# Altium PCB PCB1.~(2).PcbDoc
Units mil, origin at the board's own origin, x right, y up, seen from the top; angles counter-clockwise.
Board outline 1968 x 1968 mil, 4 copper layers (Top Layer, Internal Plane 1, Internal Plane 2, Bottom Layer), stack 18.2 mil thick; 12 components, 11 nets, 37 pads, 0 vias.
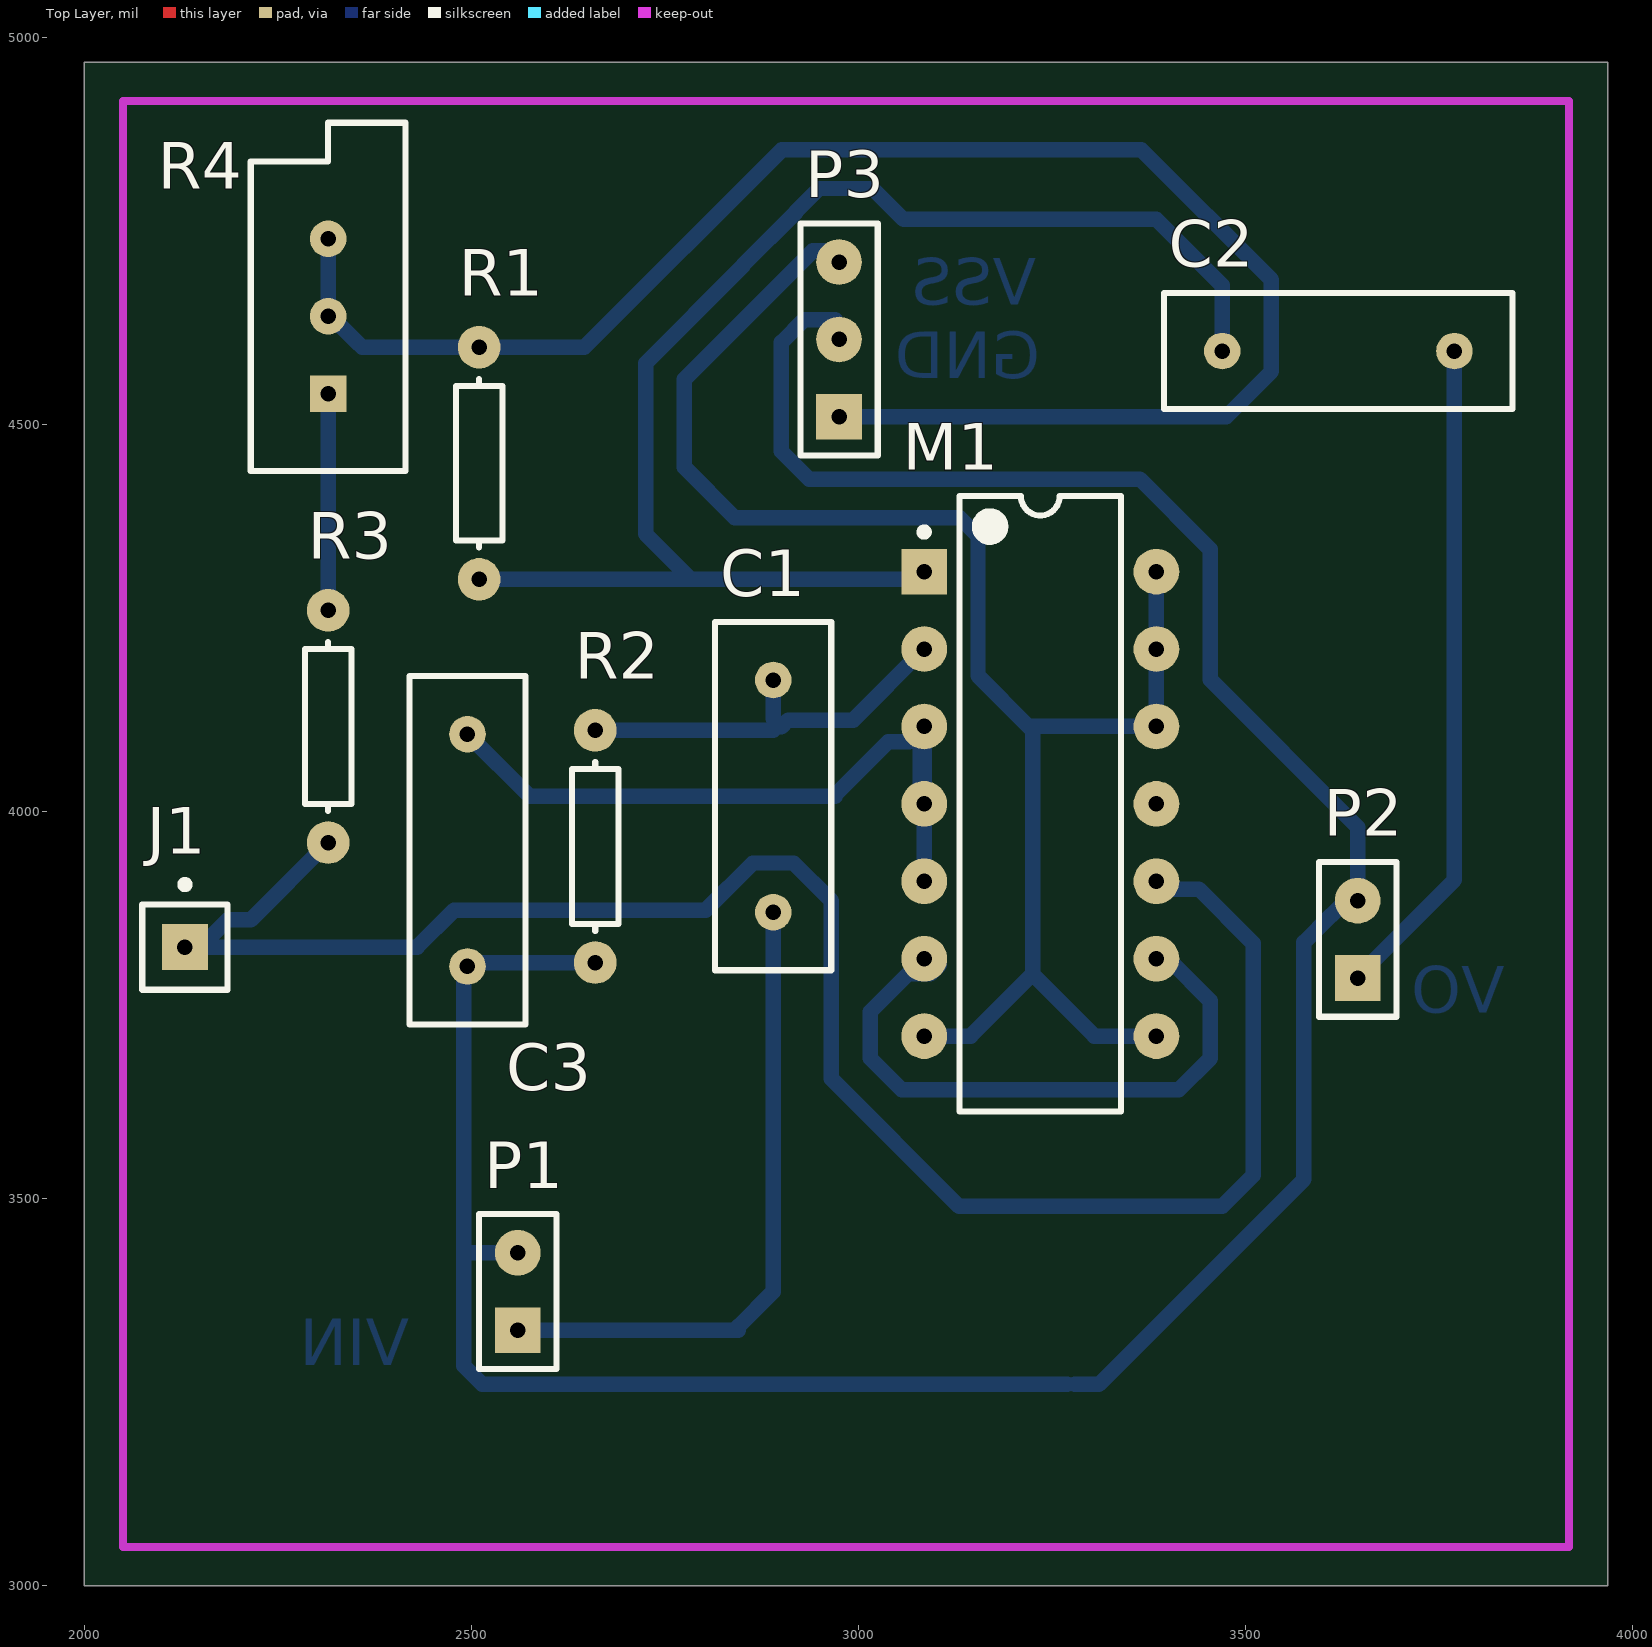
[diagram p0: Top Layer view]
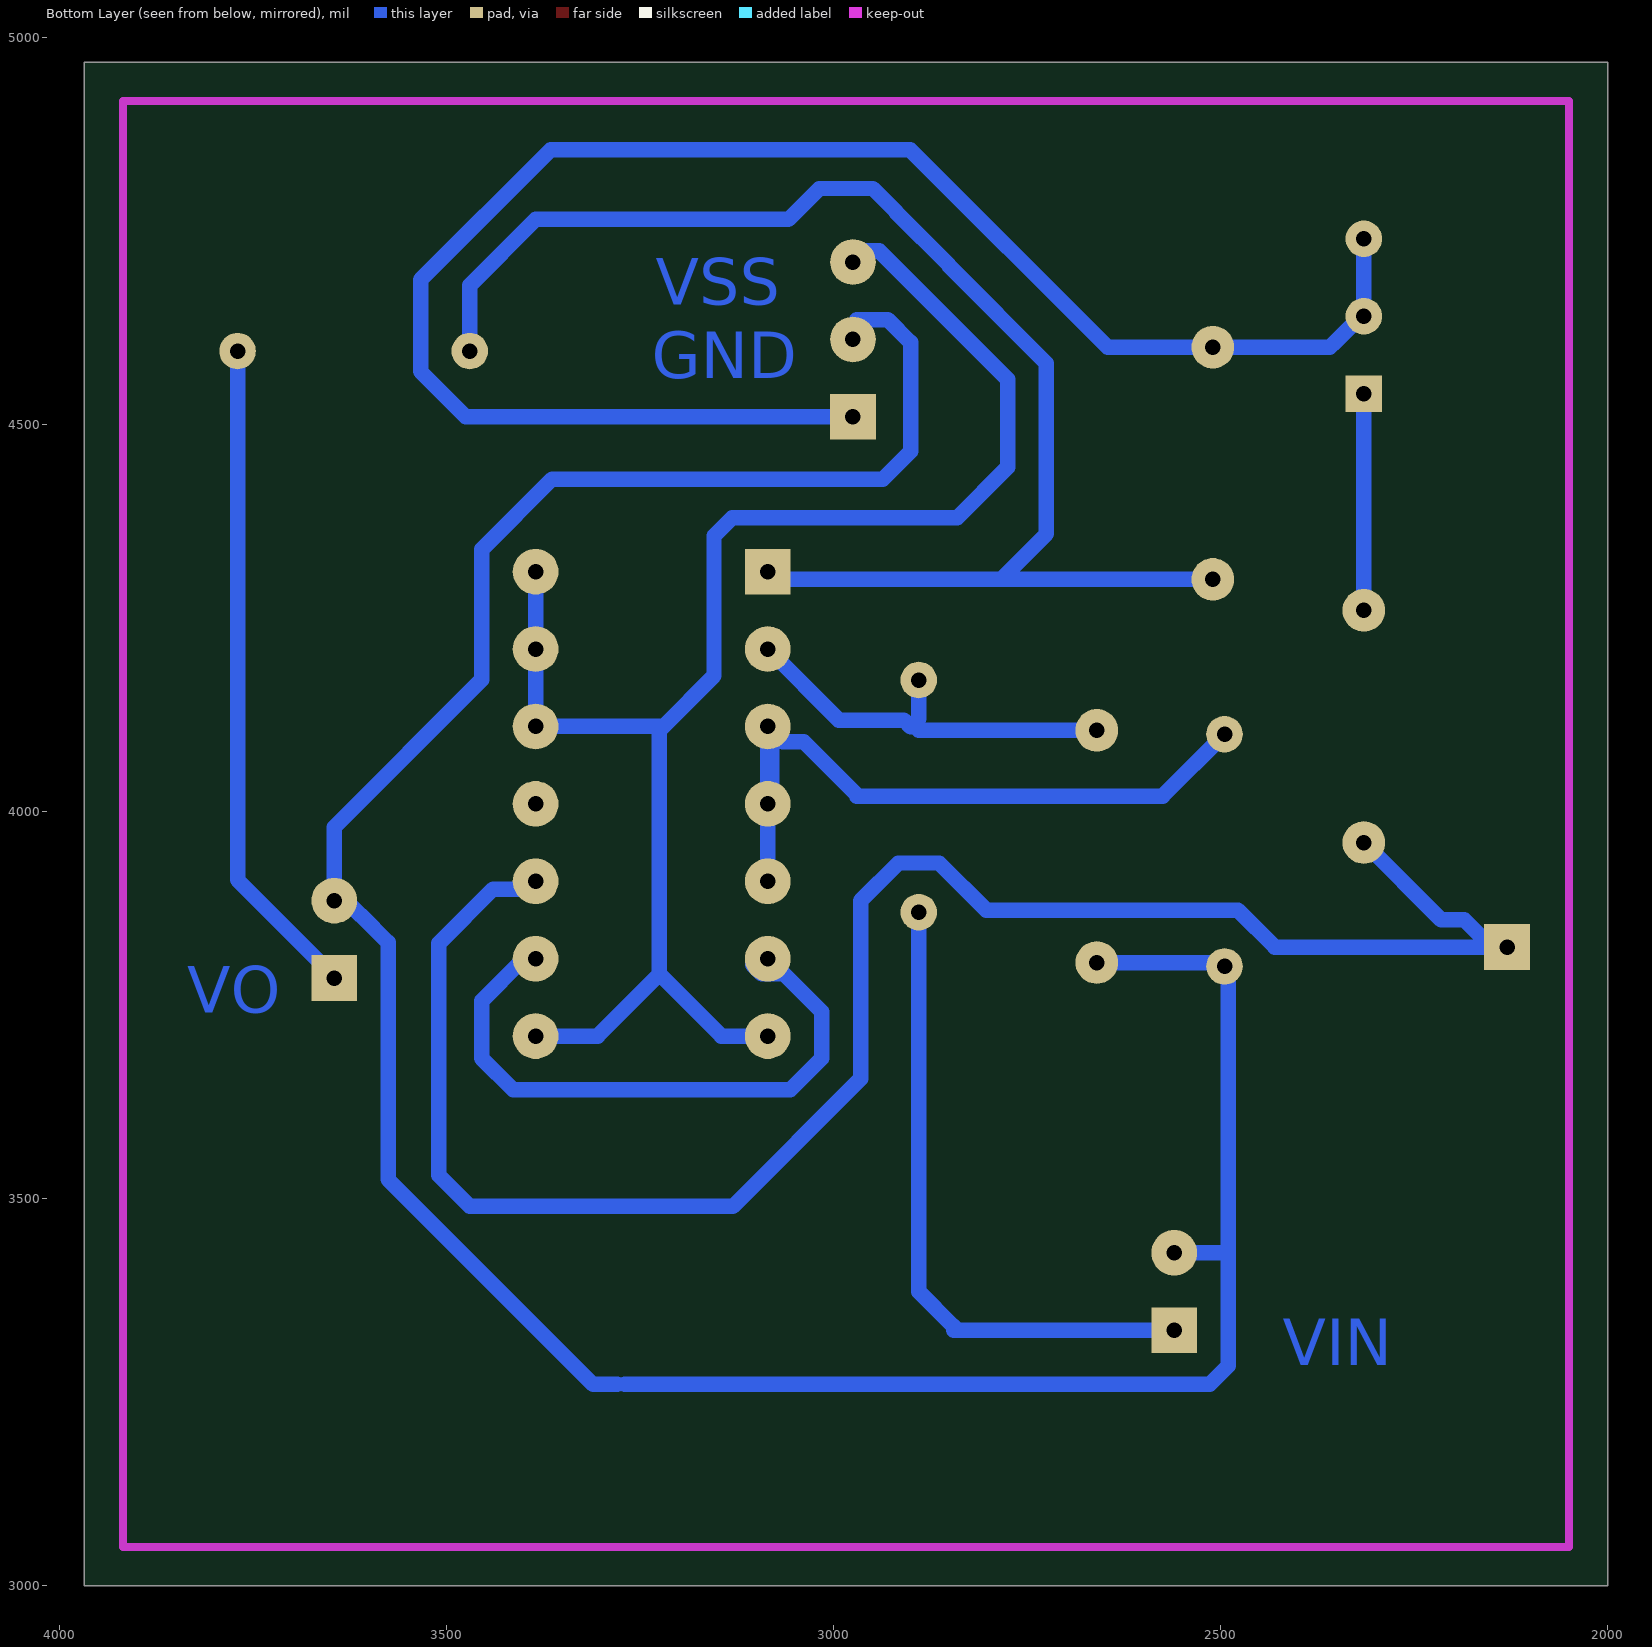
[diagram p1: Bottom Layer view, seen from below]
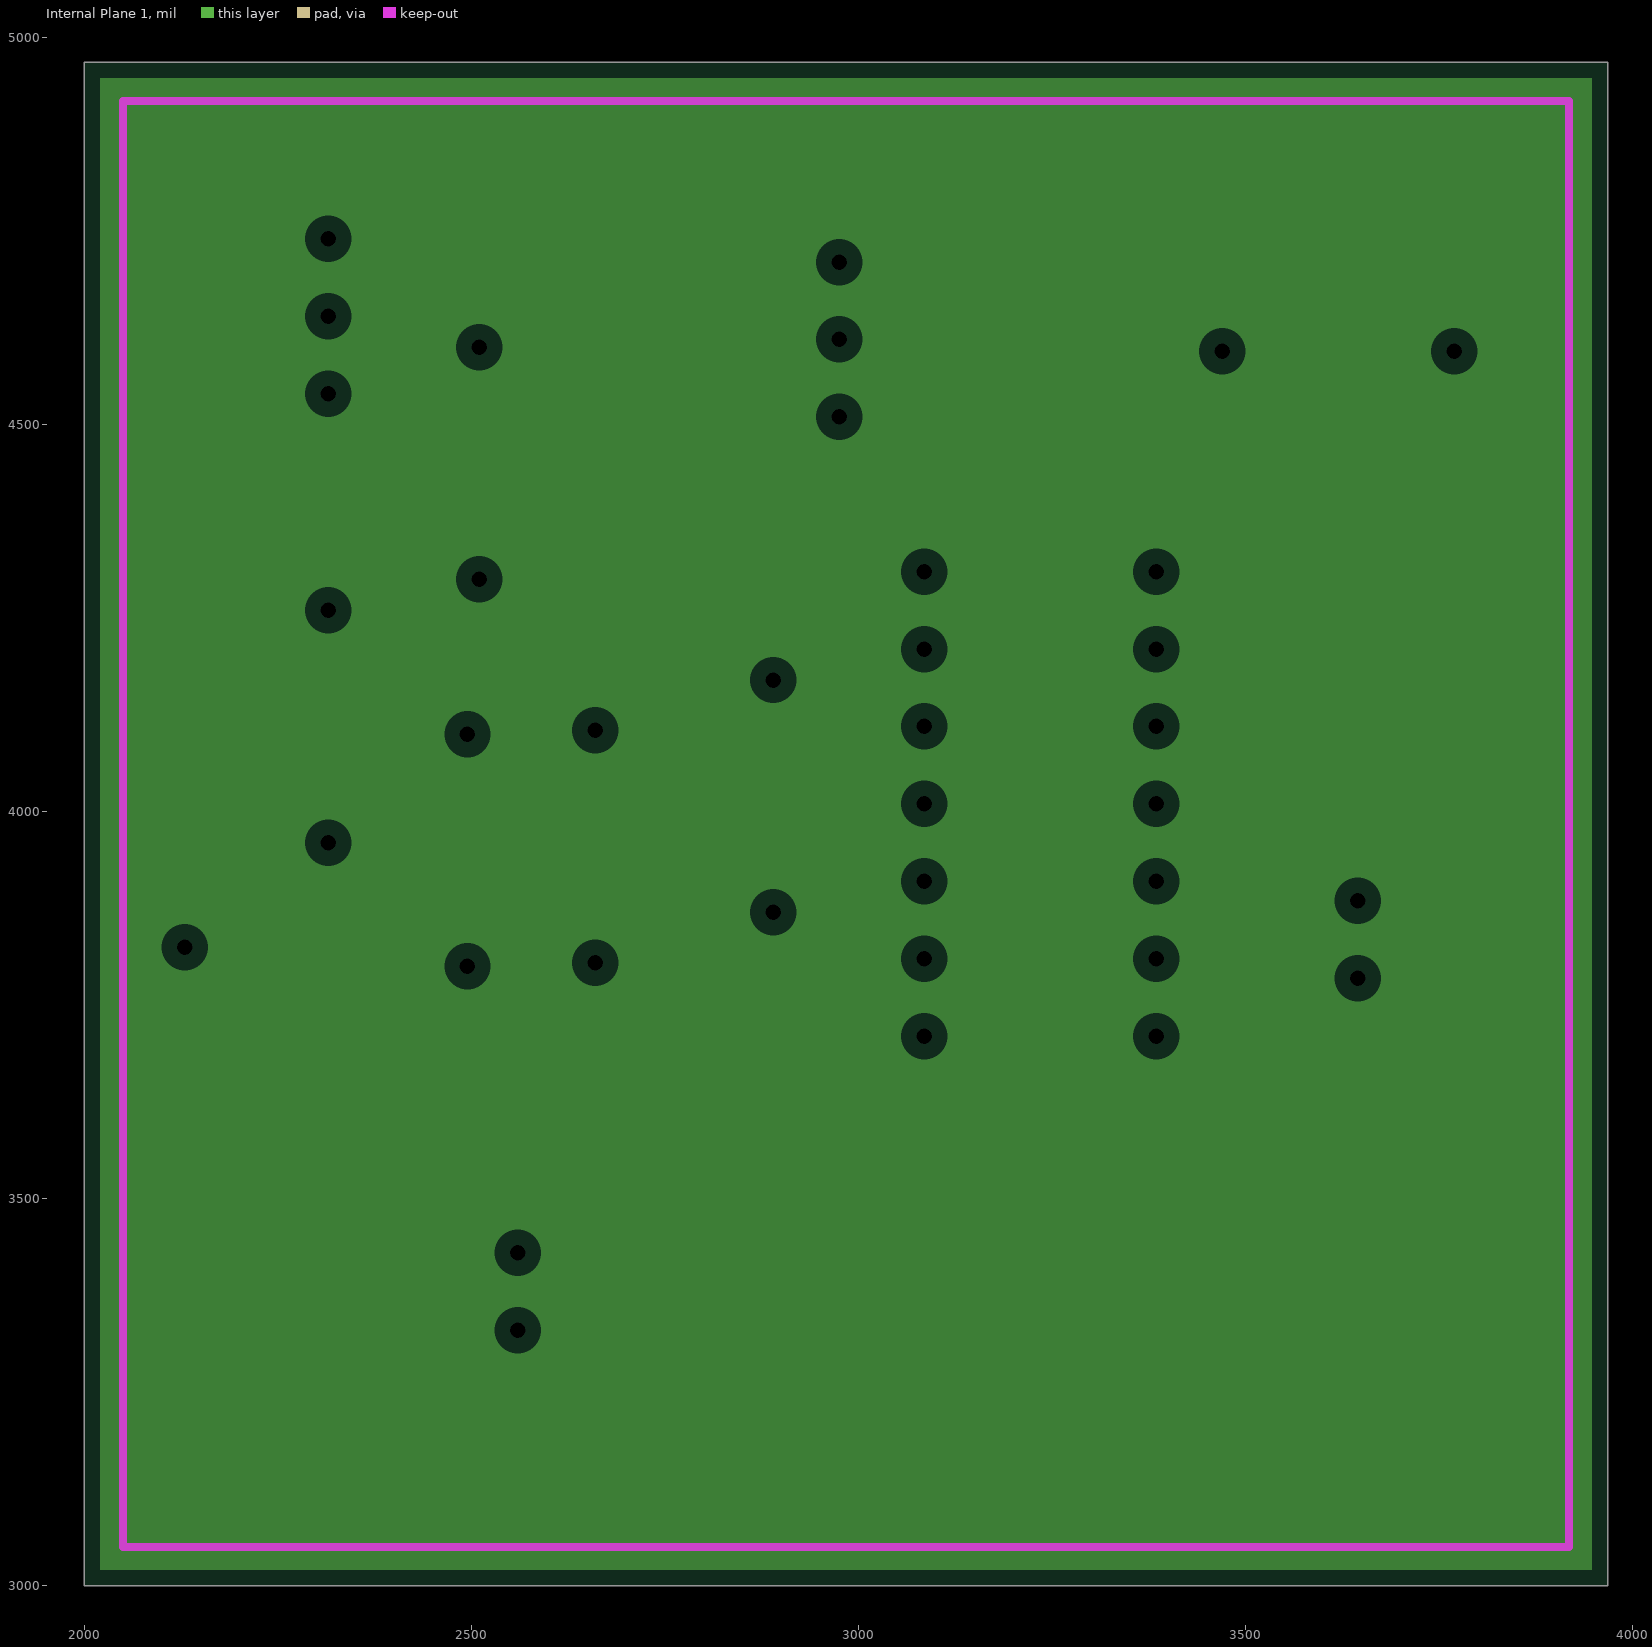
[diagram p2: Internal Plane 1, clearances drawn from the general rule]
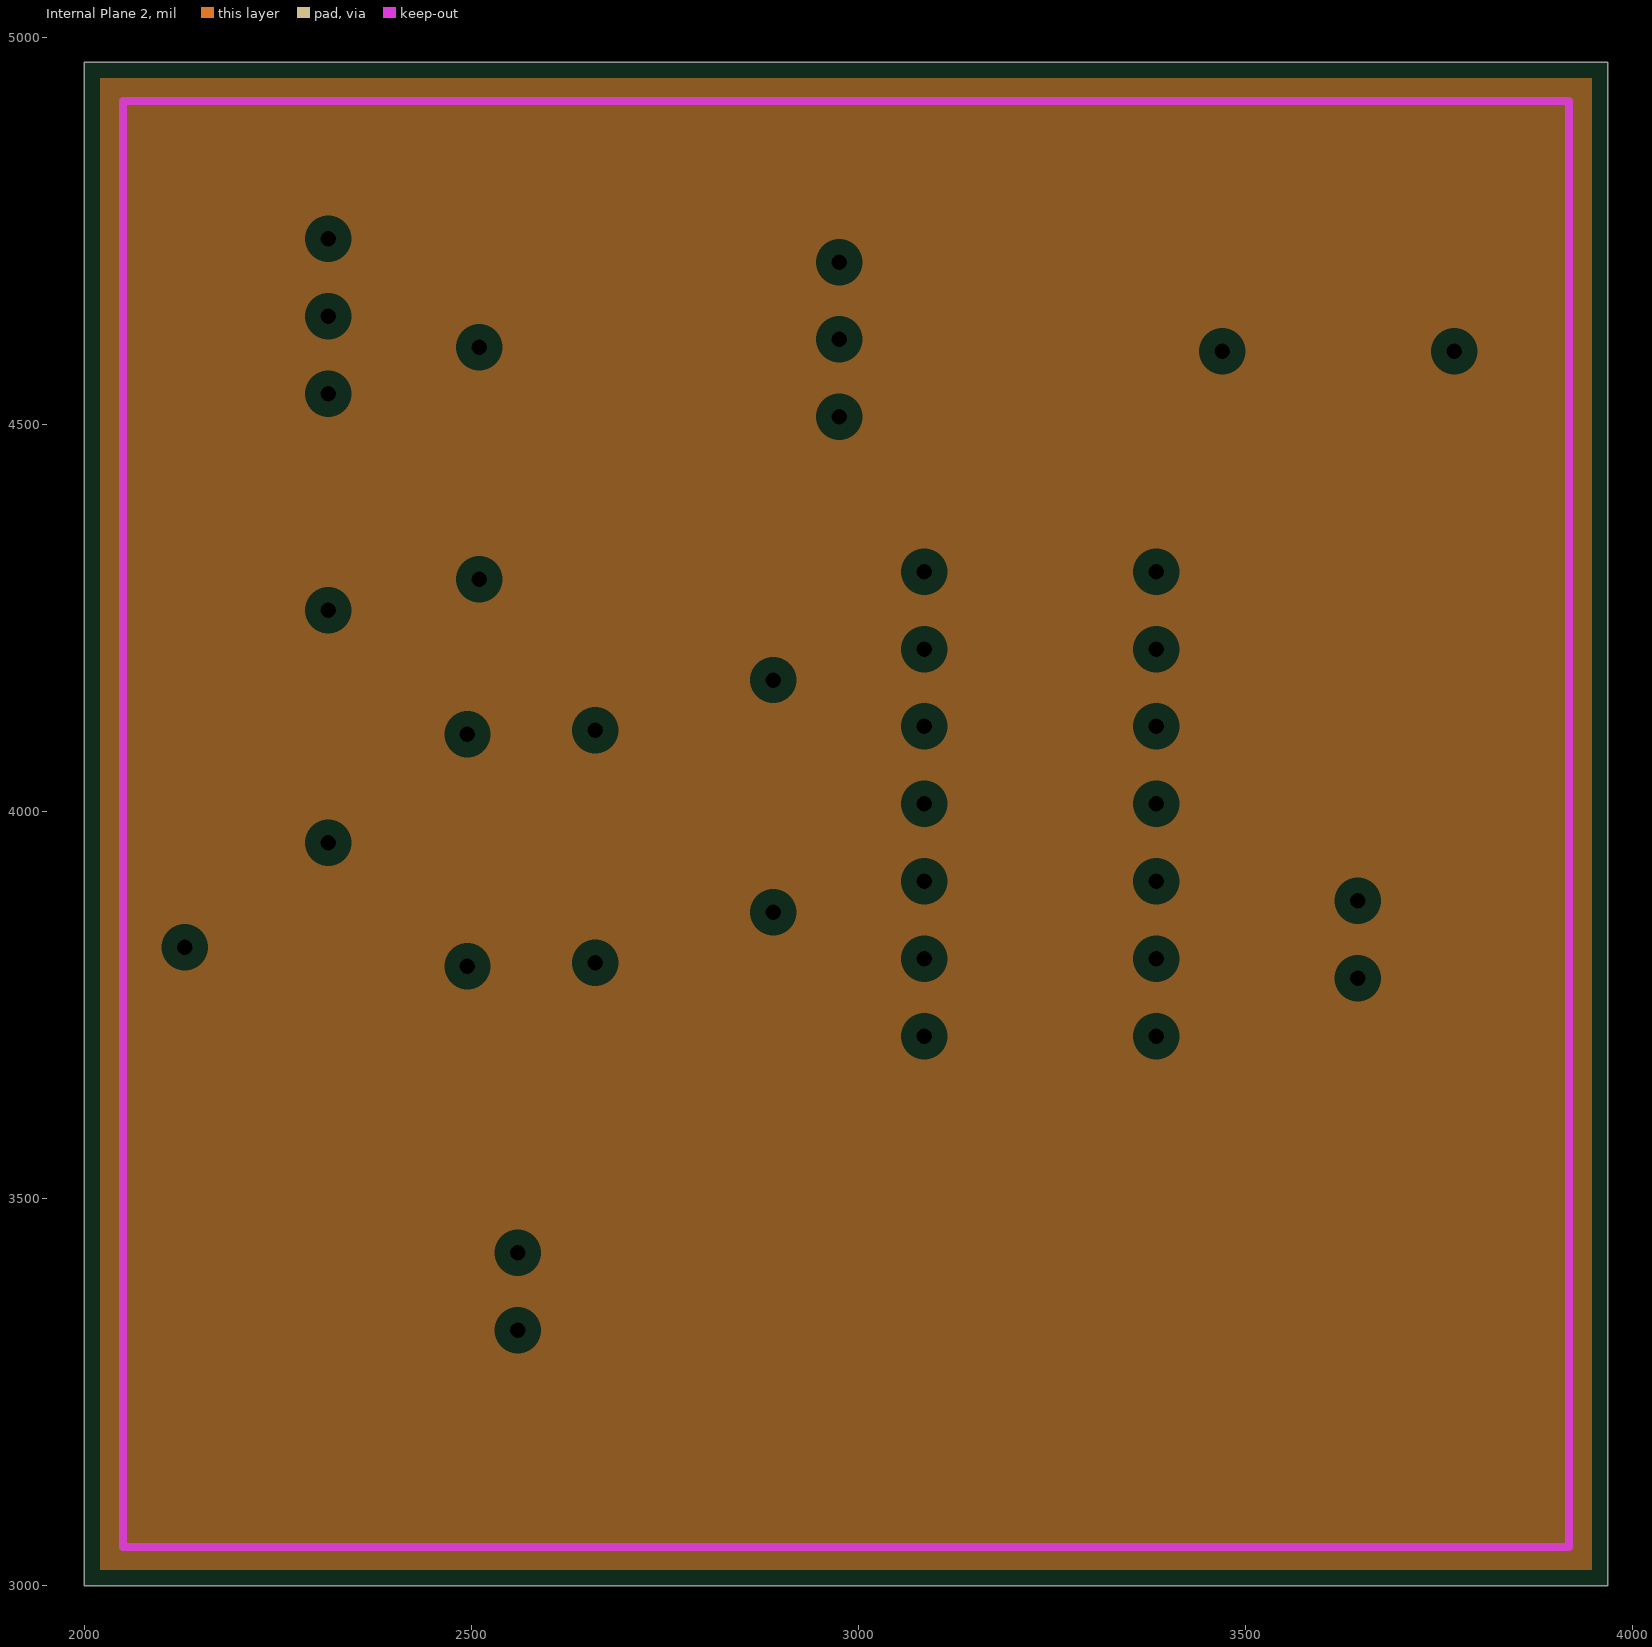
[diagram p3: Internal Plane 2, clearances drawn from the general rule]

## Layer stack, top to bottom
Top Solder: solder mask 0.4, Solder Resist, Dk 3.5
Top Layer: signal copper 1.4
Internal Plane 1: plane copper 1.4
Internal Plane 2: plane copper 1.4
Dielectric 1: dielectric 12.6, FR-4, Dk 4.8
Bottom Layer: signal copper 1.4
Bottom Solder: solder mask 0.4, Solder Resist, Dk 3.5

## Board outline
2000,3000 3968,3000 3968,4968 2000,4968

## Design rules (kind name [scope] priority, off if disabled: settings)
Clearance [All] p1: gap=30
PlaneClearance [All] p1: clearance=20
PlaneConnect [All] p1: planeconnectstyle=Relief reliefexpansion=20 reliefentries=4 reliefconductorwidth=10 reliefairgap=10
PolygonConnect [All] p1: connectstyle=Relief reliefconductorwidth=10 reliefentries=4 polygonreliefangle="90 Angle" airgapwidth=10
RoutingVias [All] p1: holewidth=32 width=62 viastyle="Through Hole" minholewidth=28 minwidth=50 maxholewidth=28 maxwidth=50
SolderMaskExpansion [All] p1: expansion=4
Width [All] p1: maxlimit=20 minlimit=20 preferedwidth=20
28 further rules are at their usual default settings.

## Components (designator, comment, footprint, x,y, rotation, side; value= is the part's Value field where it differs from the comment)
C1 "Cap" RAD-0.3 2890,4020 r90 top
C2 "Cap" RAD-0.3 3620,4595 r0 top
C3 "Cap" RAD-0.3 2495,3950 r90 top
J1 "Socket" PIN1 2130,3825 r0 top
M1 "ALD1106" DIP-14 3235,4010 r0 top
P1 "Header 2" HDR1X2 2560,3330 r90 top
P2 "Header 2" HDR1X2 3645,3785 r90 top
P3 "Header 3" HDR1X3 2975,4510 r90 top
R1 "Res1" AXIAL-0.3 2510,4450 r90 top
R2 "Res1" AXIAL-0.3 2660,3955 r90 top
R3 "Res1" AXIAL-0.3 2315,4110 r90 top
R4 "RPot" VR5 2315,4640 r90 top

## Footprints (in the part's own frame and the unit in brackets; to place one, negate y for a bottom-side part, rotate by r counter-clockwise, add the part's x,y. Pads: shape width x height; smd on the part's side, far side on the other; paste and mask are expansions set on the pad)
AXIAL-0.3 [mm] "Axial Device, Thru-Hole; 2 Leads; 0.3 in Pin Spacing"
  round 1.4 hole 0.508: 1(-3.81,0) 2(3.81,0)
  silkscreen extent -2.77,-0.76 2.77,0.76
DIP-14 [mm] "DIP, 14-Pin, Row Spacing 7.62 mm, Pitch 2.54 mm"
  rect 1.5x1.5 hole 0.508: 1(-3.81,7.62)
  round 1.5 hole 0.508: 2(-3.81,5.08) 3(-3.81,2.54) 4(-3.81,0) 5(-3.81,-2.54) 6(-3.81,-5.08) 7(-3.81,-7.62) 8(3.81,-7.62) 9(3.81,-5.08) 10(3.81,-2.54) 11(3.81,0) 12(3.81,2.54) 13(3.81,5.08) 14(3.81,7.62)
  silkscreen extent -3.93,-10.1 2.65,10.1, body extent -3.6,-10.1 3.6,10.1, height 5.08
HDR1X2 [mm] "Connector; Header; 2 Position"
  rect 1.5x1.5 hole 0.508: 1(0,0)
  round 1.5 hole 0.508: 2(2.54,0)
  silkscreen extent -1.27,-1.27 3.81,1.27
HDR1X3 [mm] "Connector; Header; 3 Position"
  rect 1.5x1.5 hole 0.508: 1(0,0)
  round 1.5 hole 0.508: 2(2.54,0) 3(5.08,0)
  silkscreen extent -1.27,-1.27 6.35,1.27
PIN1 [mm] "Connector; Plug"
  rect 1.5x1.5 hole 0.508: 1(0,0)
  silkscreen extent -1.4,-1.4 1.4,2.17
RAD-0.3 [mm] "Radial Cap, Thru-Hole; 2 Leads; 0.3 in Pin Spacing"
  round 1.2 hole 0.508: 1(-3.81,0) 2(3.81,0)
  silkscreen extent -5.71,-1.91 5.71,1.91
VR5 [mm] "Thru-Hole; 3 Leads"
  rect 1.2x1.2 hole 0.508: 1(-2.54,0)
  round 1.2 hole 0.508: 2(0,0) 3(2.54,0)
  silkscreen extent -5.08,-2.54 6.35,2.54

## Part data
C1 C2 C3: "Capacitor"
M1: "Quad N-channel matched MOSFET array"
P1 P2: "Header, 2-Pin"
P3: "Header, 3-Pin"
R1 R2 R3: "Resistor"
R4: "Potentiometer"

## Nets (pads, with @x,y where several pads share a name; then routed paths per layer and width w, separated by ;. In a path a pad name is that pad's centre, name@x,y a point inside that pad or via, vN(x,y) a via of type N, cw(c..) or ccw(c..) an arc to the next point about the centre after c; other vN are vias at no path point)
GND: C3.1 P1.2 P2.2 P3.2 R2.1 | length 3681.4
  Bottom Layer w20: 2490,3404.53 2490,3430 ; 2490.47,3404.53 2490.47,3283.9 2513.9,3260.47 3269.76,3260.47 ; C3.1 2490,3800 2490,3430 ; C3.1@2500,3805 R2.1@2635.71,3805 ; P1.2 2490,3430 ; P3.2@2970,4635.47 2929.76,4635.47 2900.47,4606.18 2900.47,4465.47 2936.42,4429.53 3363.8,4429.53 3454.53,4338.8 3454.53,4170.47 3645,3980 P2.2 3630,3885 3610.47,3865.47 3609.85,3865.47 3575.47,3831.1 3575.47,3524.76 3310.71,3260 3279.29,3260
NetC1_1: C1.1 P1.1 | length 838.6
  Bottom Layer w20: P1.1 2845,3330 ; 2845,3335 2890,3380 C1.1
NetC1_2: C1.2 M1.2 R2.2 | length 501.1
  Bottom Layer w20: R2.2 2740,4105 ; 2745,4105 2890,4105 ; 2890,4120 C1.2 ; 2900.48,4109.52 2909.29,4118.33 2993.33,4118.33 M1.2
NetC2_1: C2.1 M1.1 R1.1 | length 1873.9
  Bottom Layer w20: R1.1 3075,4300 M1.1 ; 2783.82,4300 2725,4358.82 2725,4579.04 2850.47,4704.51 2850.47,4705.47 2920,4775 2920,4775.71 2949.29,4805 3018.33,4805 3058.33,4765 3385,4765 3470,4680 C2.1 ; 2835,4300 2850,4300
NetC2_2: C2.2 P2.1 | length 869.1
  Bottom Layer w20: P2.1 3645,3800 3658.33,3800 3770,3911.67 3770,4314.55 ; 3770,4315 C2.2
NetC3_2: C3.2 M1.3 M1.4 M1.5 | length 956.8
  Bottom Layer w20: C3.2 2575,4020 2970,4020 ; 2970,4021.61 3038.86,4090.47 3065.47,4090.47 M1.3@3080,4105 ; M1.5 M1.4 ; M1.3@3080,4105 3080,4015 M1.4 ; M1.3@3080,4105 M1.3 M1.4
NetJ1_1: J1.1 M1.10 R3.1 | length 2445
  Bottom Layer w20: J1.1 J1.1@2150,3825 ; R3.1 2215,3860 2185,3860 J1.1@2150,3825 ; M1.10 3385,3900 3440,3900 3510,3830 3510,3530 3470,3490 3130,3490 2965,3655 2964.98,3885 2916.35,3933.62 2863.65,3933.62 2802.58,3872.56 2477.58,3872.56 2430.02,3825 2180,3825 J1.1@2150,3825
NetM1_4: M1.7 M1.8 M1.12 M1.13 M1.14 P3.3 | length 2120.1
  Bottom Layer w20: P3.3@2970,4724.53 2941.2,4724.53 2775,4558.33 2775,4445 2840.47,4379.53 3131.1,4379.53 3154.53,4356.1 3154.53,4175.47 3220,4110 ; M1.7 3145,3710 3225,3790 ; M1.8 3305,3710 3225,3790 ; M1.14 M1.13 M1.12 3220,4110 ; 3220,4110 3225,4105 3225,3790
NetM1_6: M1.6 M1.9 | length 822.7
  Bottom Layer w20: M1.6 3104.53,3810 3104.53,3801.91 3093.09,3790.47 3064.29,3790.47 3015.47,3741.66 3015.47,3681.2 3056.2,3640.47 3413.8,3640.47 3454.53,3681.2 3454.53,3755.47 M1.9@3402.5,3807.5
NetP3_1: P3.1 R1.2 R4.2 R4.3 | length 2206.6
  Bottom Layer w20: R4.3 R4.2 2318.81,4640 2355.19,4603.62 ; 2358.81,4600 R1.2 2545,4600 2645.96,4600 2900.96,4855 3365.71,4855 3533.62,4687.09 3533.62,4568.65 3474.98,4510 P3.1
NetR3_2: R3.2 R4.1 | length 270
  Bottom Layer w20: R3.2@2315,4270 R4.1
pads on no net: M1.11

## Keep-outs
Keep-Out Layer:
  lines w10: 2050,3050 3918,3050 3918,4918 2050,4918 2050,3050

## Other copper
Bottom Layer:
  text "VSS" at 3230,4655 h60
  text "GND" at 3235,4560 h60
  text "VO" at 3835,3740 h60
  text "VIN" at 2420,3285 h60

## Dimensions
2050,3050 to 3918,3050 on Mechanical 1
2050,3050 to 2050,4918 on Mechanical 1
